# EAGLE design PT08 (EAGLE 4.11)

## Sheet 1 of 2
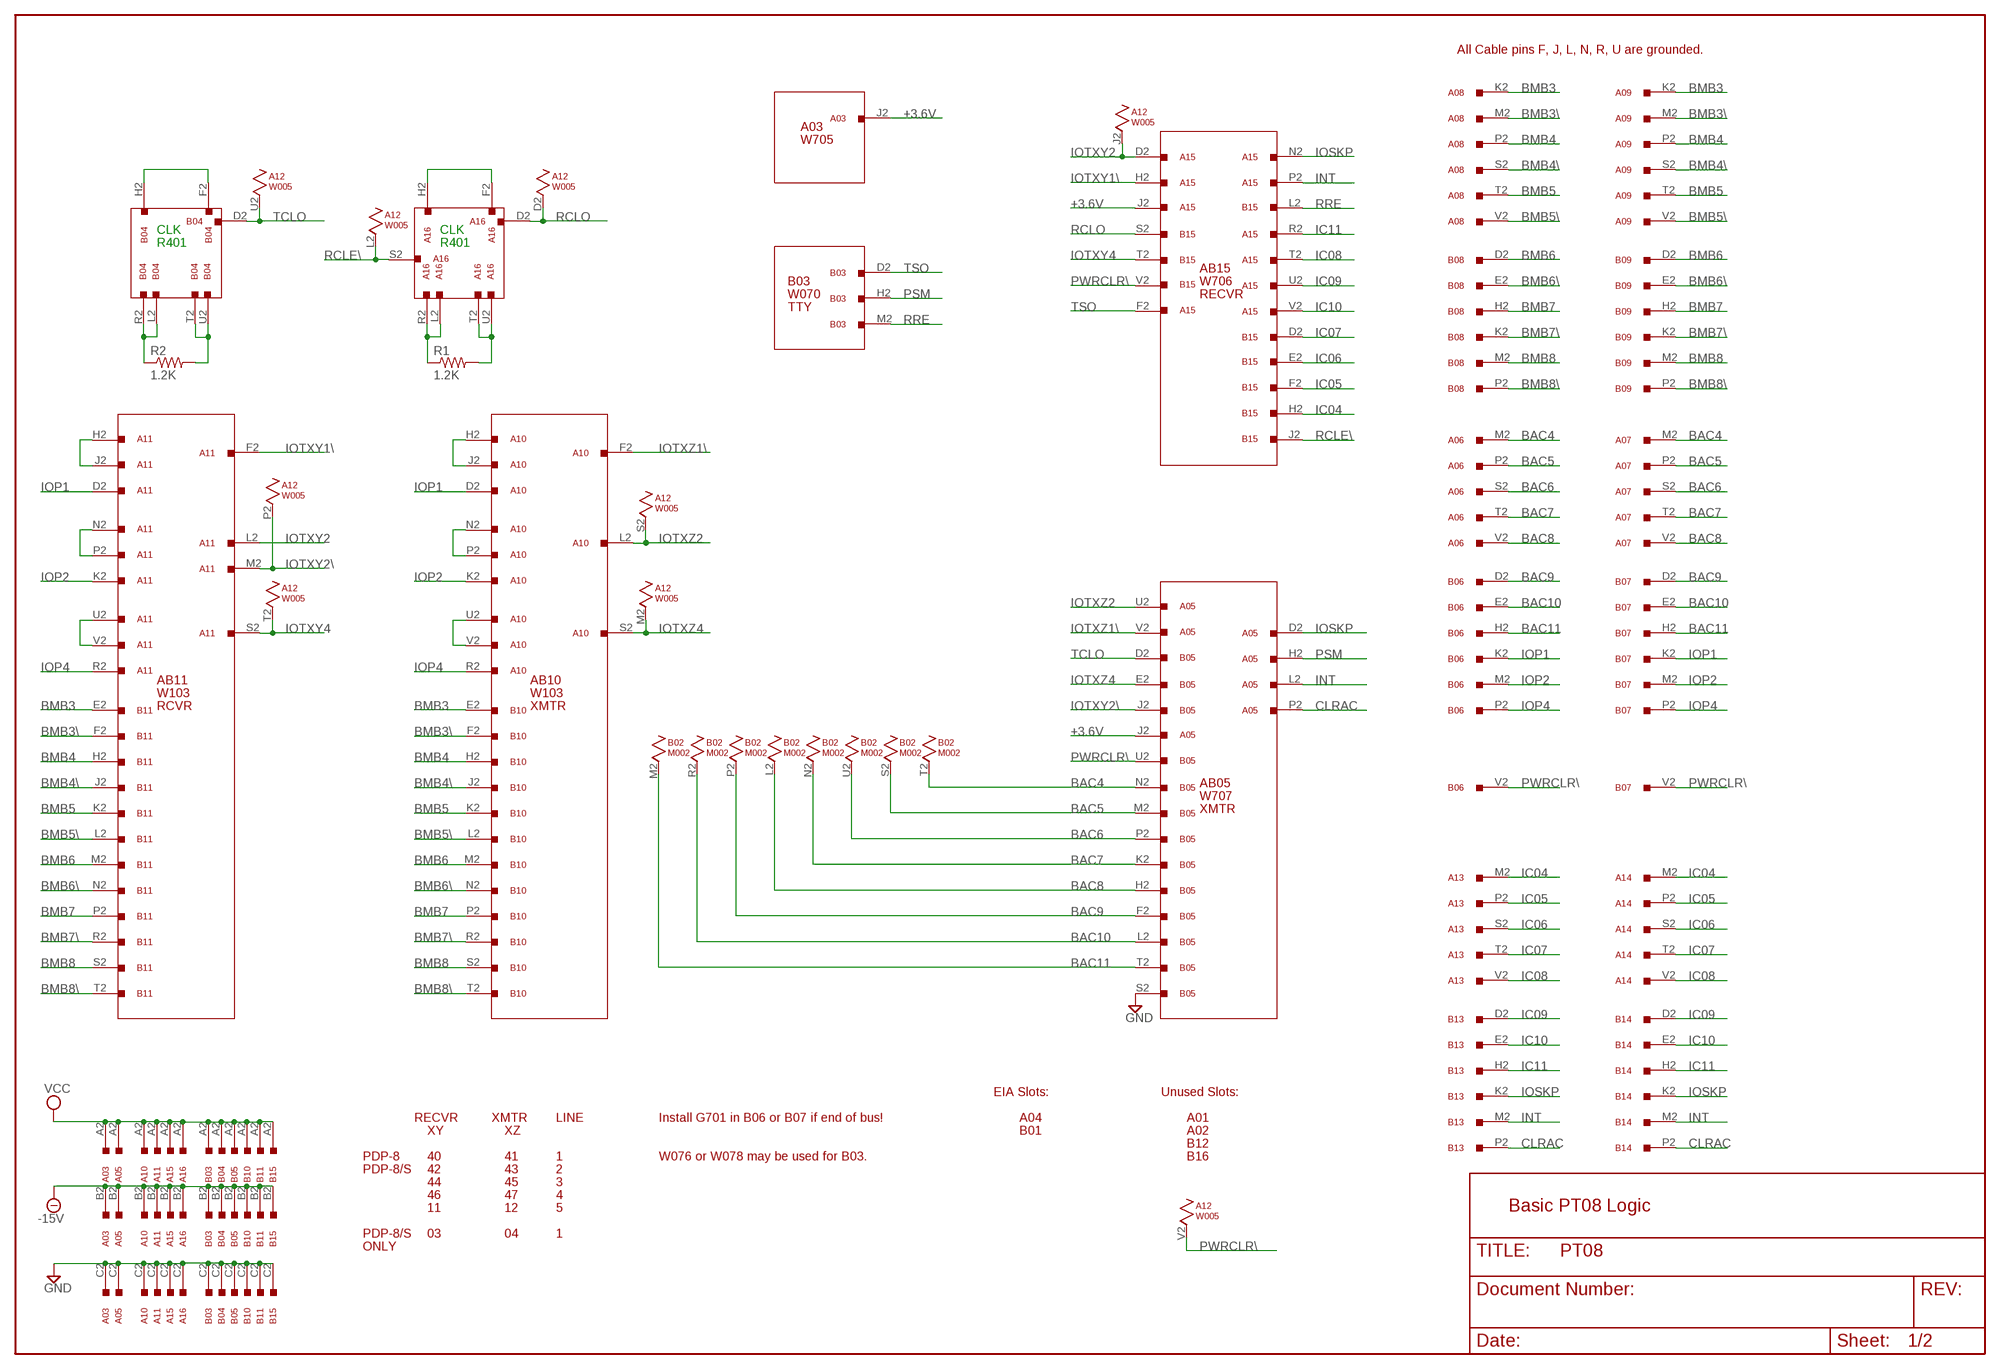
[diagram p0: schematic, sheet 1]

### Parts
A01  H807  [H807]
A02  H807  [H807]
A03  W705  W023  [H807]
A05  W707  W023  [H807]
A06  W011  [H807]
A07  W011  [H807]
A08  W011  [H807]
A09  W011  [H807]
A10  W103  W023  [H807]
A11  W103  W023  [H807]
A12  W005  [H807]
A13  W011  [H807]
A14  W011  [H807]
A15  W706  W023  [H807]
A16  R401  W023  [H807]
B02  M002  [H807]
B03  W076  W023  [H807]
B04  R401  W023  [H807]
B05  W707  W023  [H807]
B06  W011  [H807]
B07  W011  [H807]
B08  W011  [H807]
B09  W011  [H807]
B10  W103  W023  [H807]
B11  W103  W023  [H807]
B12  H807  [H807]
B13  W011  [H807]
B14  W011  [H807]
B15  W706  W023  [H807]
B16  H807  [H807]
R1  1.2K  R-US_0207/10  [0207/10]
R2  1.2K  R-US_0207/10  [0207/10]

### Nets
+3.6V: A03.J2 A05.J2 A15.J2
-15V [Power]: A03.B2 A05.B2 A10.B2 A11.B2 A15.B2 A16.B2 B03.B2 B04.B2 B05.B2 B10.B2 B11.B2 B15.B2 ; also sheet 2
BAC4: A06.M2 A07.M2 B02.T2 B05.N2
BAC5: A06.P2 A07.P2 B02.S2 B05.M2
BAC6: A06.S2 A07.S2 B02.U2 B05.P2
BAC7: A06.T2 A07.T2 B02.N2 B05.K2
BAC8: A06.V2 A07.V2 B02.L2 B05.H2
BAC9: B02.P2 B05.F2 B06.D2 B07.D2
BAC10: B02.R2 B05.L2 B06.E2 B07.E2
BAC11: B02.M2 B05.T2 B06.H2 B07.H2
BMB3: A08.K2 A09.K2 B10.E2 B11.E2
BMB3\: A08.M2 A09.M2 B10.F2 B11.F2
BMB4: A08.P2 A09.P2 B10.H2 B11.H2
BMB4\: A08.S2 A09.S2 B10.J2 B11.J2
BMB5: A08.T2 A09.T2 B10.K2 B11.K2
BMB5\: A08.V2 A09.V2 B10.L2 B11.L2
BMB6: B08.D2 B09.D2 B10.M2 B11.M2
BMB6\: B08.E2 B09.E2 B10.N2 B11.N2
BMB7: B08.H2 B09.H2 B10.P2 B11.P2
BMB7\: B08.K2 B09.K2 B10.R2 B11.R2
BMB8: B08.M2 B09.M2 B10.S2 B11.S2
BMB8\: B08.P2 B09.P2 B10.T2 B11.T2
CLRAC: A05.P2 B13.P2 B14.P2
GND [Power]: A03.C2 A05.C2 A10.C2 A11.C2 A15.C2 A16.C2 B03.C2 B04.C2 B05.C2 B05.S2 B10.C2 B11.C2 B15.C2 ; also sheet 2
IC04: A13.M2 A14.M2 B15.H2
IC05: A13.P2 A14.P2 B15.F2
IC06: A13.S2 A14.S2 B15.E2
IC07: A13.T2 A14.T2 B15.D2
IC08: A13.V2 A14.V2 A15.T2
IC09: A15.U2 B13.D2 B14.D2
IC10: A15.V2 B13.E2 B14.E2
IC11: A15.R2 B13.H2 B14.H2
INT: A05.L2 A15.P2 B13.M2 B14.M2
IOP1: A10.D2 A11.D2 B06.K2 B07.K2
IOP2: A10.K2 A11.K2 B06.M2 B07.M2
IOP4: A10.R2 A11.R2 B06.P2 B07.P2
IOSKP: A05.D2 A15.N2 B13.K2 B14.K2
IOTXY1\: A11.F2 A15.H2
IOTXY2: A11.L2 A12.J2 A15.D2
IOTXY2\: A11.M2 A12.P2 B05.J2
IOTXY4: A11.S2 A12.T2 B15.T2
IOTXZ1\: A05.V2 A10.F2
IOTXZ2: A05.U2 A10.L2 A12.S2
IOTXZ4: A10.S2 A12.M2 B05.E2
N$1: A10.U2 A10.V2
N$2: A16.F2 A16.H2
N$3: A16.L2 A16.R2 R1.1
N$4: A16.T2 A16.U2 R1.2
N$5: A10.H2 A10.J2
N$6: B04.F2 B04.H2
N$7: B04.L2 B04.R2 R2.1
N$8: B04.T2 B04.U2 R2.2
N$9: A11.U2 A11.V2
N$10: A11.H2 A11.J2
N$11: A10.N2 A10.P2
N$12: A11.N2 A11.P2
PSM: A05.H2 B03.H2 ; also sheet 2
PWRCLR\: A12.V2 B05.U2 B06.V2 B07.V2 B15.V2
RCLE\: A12.L2 A16.S2 B15.J2
RCLO: A12.D2 A16.D2 B15.S2
RRE: B03.M2 B15.L2
TCLO: A12.U2 B04.D2 B05.D2
TSO: A15.F2 B03.D2 ; also sheet 2
VCC [Power]: A03.A2 A05.A2 A10.A2 A11.A2 A15.A2 A16.A2 B03.A2 B04.A2 B05.A2 B10.A2 B11.A2 B15.A2 ; also sheet 2
Unconnected: A03.D2 A03.E2 A03.F2 A03.H2 A03.K2 A03.L2 A03.M2 A03.N2 A03.P2 A03.R2 A03.S2 A03.T2 A03.U2 A03.V2 A05.E2 A05.F2 A05.K2 A05.M2 A05.N2 A05.R2 A05.S2 A05.T2 A06.D2 A06.E2 A06.H2 A06.K2 A07.D2 A07.E2 A07.H2 A07.K2 A08.D2 A08.E2 A08.H2 A09.D2 A09.E2 A09.H2 A10.E2 A10.M2 A10.T2 A11.E2 A11.T2 A12.E2 A12.F2 A12.H2 A12.K2 A12.N2 A12.R2 A13.D2 A13.E2 A13.H2 A13.K2 A14.D2 A14.E2 A14.H2 A14.K2 A15.E2 A15.K2 A15.L2 A15.M2 A15.S2 A16.E2 A16.J2 A16.K2 A16.M2 A16.N2 A16.P2 A16.V2 B02.F2 B02.H2 B02.J2 B02.K2 B02.V2 B03.F2 B03.J2 B03.L2 B03.N2 B03.R2 B03.S2 B03.T2 B03.U2 B03.V2 B04.E2 B04.J2 B04.K2 B04.M2 B04.N2 B04.P2 B04.S2 B04.V2 B05.R2 B05.V2 B06.S2 B06.T2 B07.S2 B07.T2 B08.S2 B08.T2 B08.V2 B09.S2 B09.T2 B09.V2 B10.D2 B10.U2 B10.V2 B11.D2 B11.U2 B11.V2 B13.S2 B13.T2 B13.V2 B14.S2 B14.T2 B14.V2 B15.K2 B15.M2 B15.N2 B15.P2 B15.R2 B15.U2

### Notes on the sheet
- All Cable pins F, J, L, N, R, U are grounded.
- A03
- W705
- CLK | CLK
- R401 | R401
- AB15
- B03 | W706
- W070 | RECVR
- TTY
- AB11 | AB10
- W103 | W103
- RCVR | XMTR
- AB05
- W707
- XMTR
- EIA Slots: | Unused Slots:
- RECVR | XMTR | LINE | Install G701 in B06 or B07 if end of bus! | A04
- XY | XZ | B01
- PDP-8 | 40 | 41 | 1 | W076 or W078 may be used for B03.
- PDP-8/S | 42 | 43 | 2
- 44 | 45 | 3
- 46 | 47 | 4
- 11 | 12 | 5 | Basic PT08 Logic
- PDP-8/S | 03 | 04 | 1
- ONLY

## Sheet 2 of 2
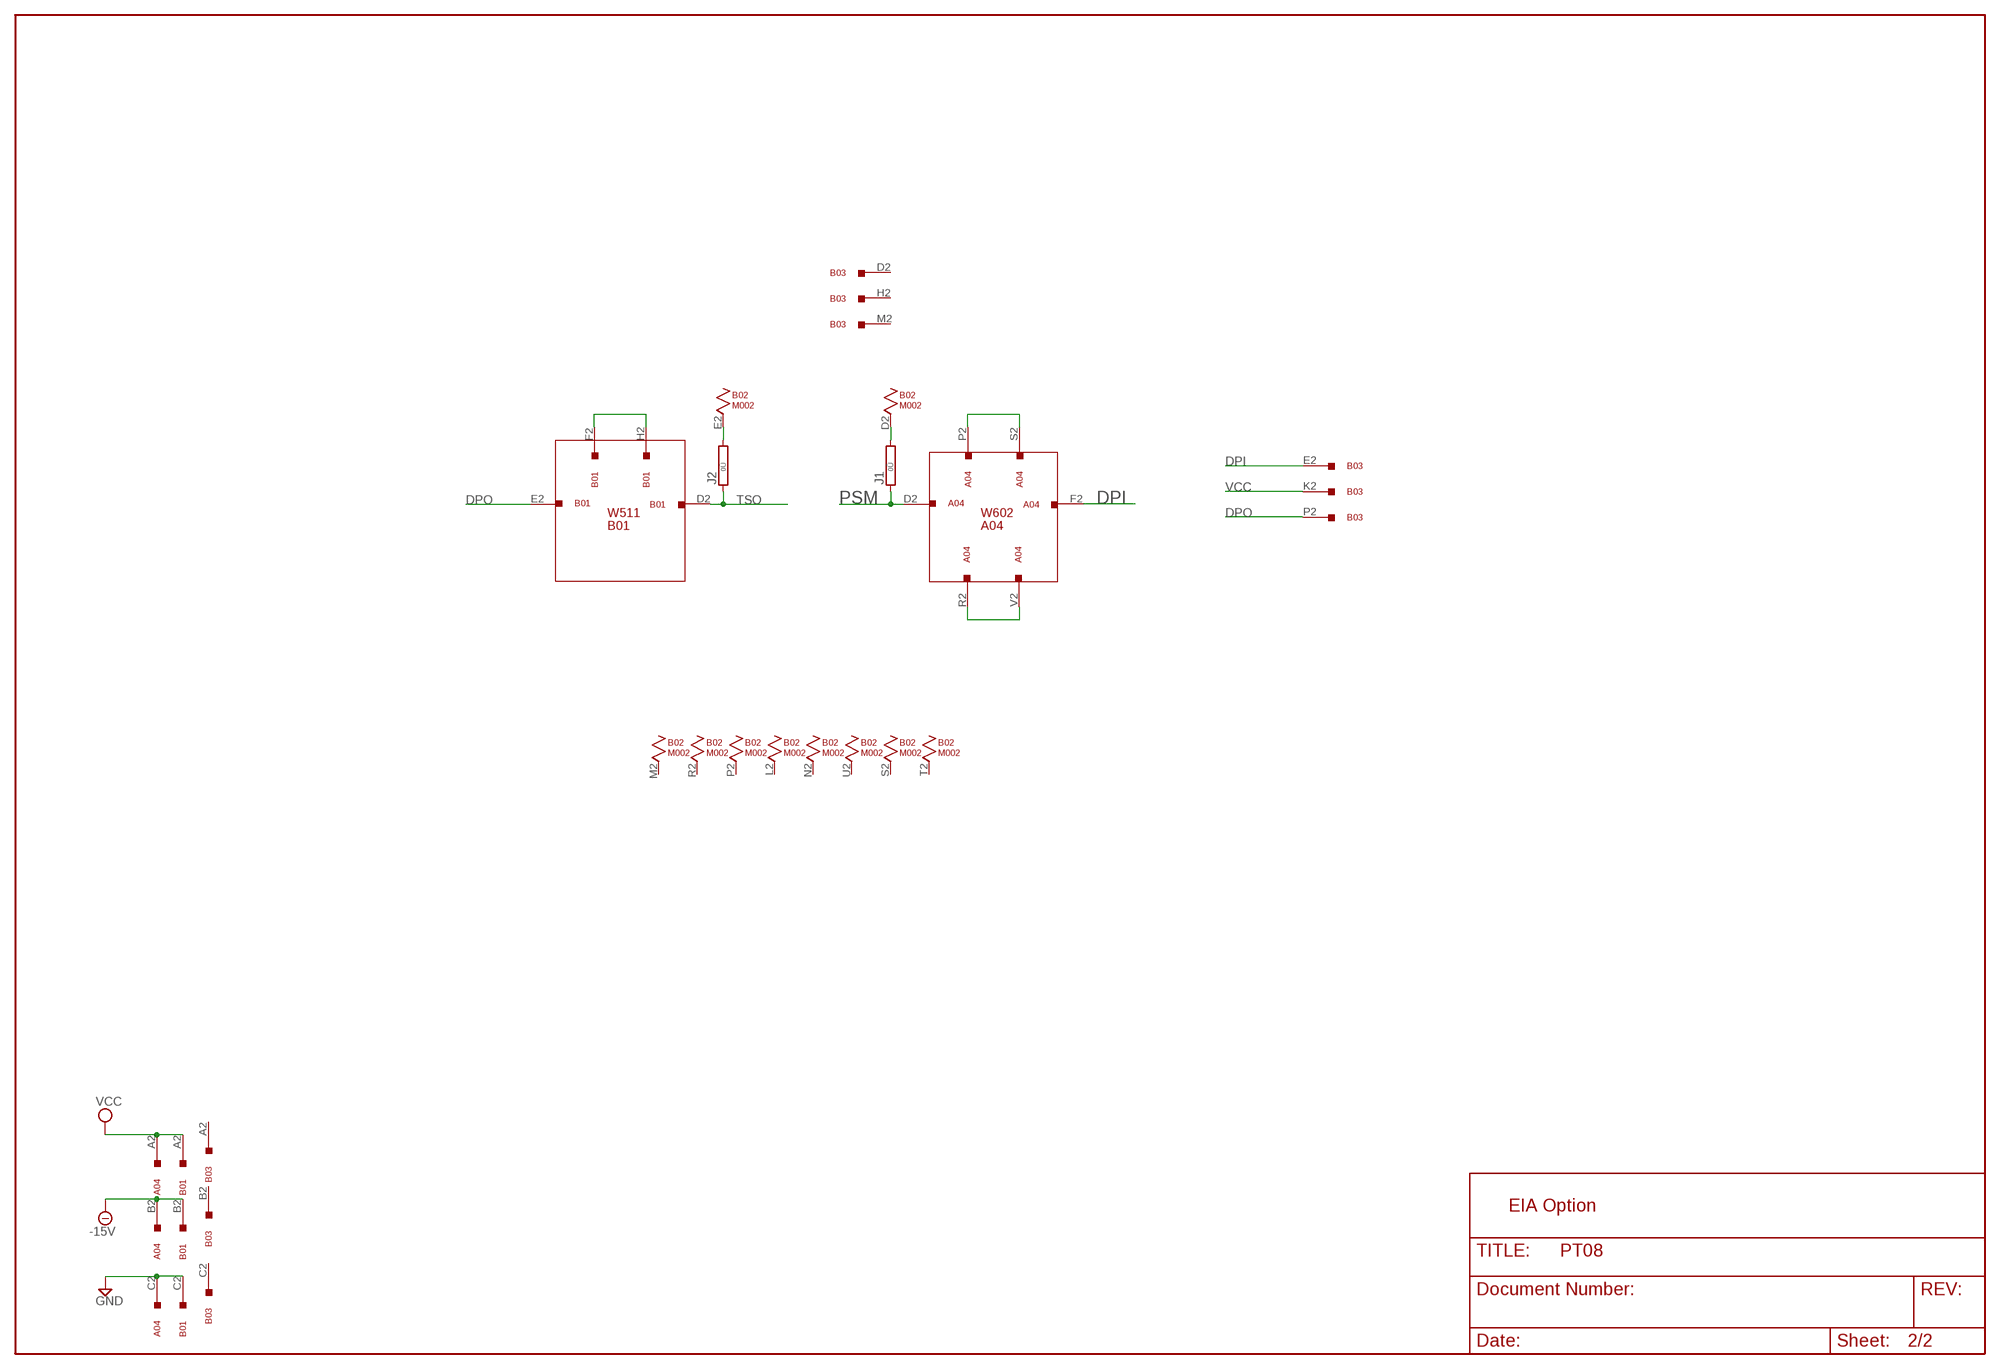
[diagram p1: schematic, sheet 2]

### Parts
A04  W602  W023  [H807]
B01  W511  W023  [H807]
J1  0R  [0R/10]
J2  0R  [0R/10]

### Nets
-15V [Power]: A04.B2 B01.B2 ; also sheet 1
DPI: A04.F2 B03.E2
DPO: B01.E2 B03.P2
GND [Power]: A04.C2 B01.C2 ; also sheet 1
N$13: A04.P2 A04.S2
N$14: A04.R2 A04.V2
N$15: B02.D2 J1.2
N$16: B01.F2 B01.H2
N$17: B02.E2 J2.2
PSM: A04.D2 J1.1 ; also sheet 1
TSO: B01.D2 J2.1 ; also sheet 1
VCC [Power]: A04.A2 B01.A2 B03.K2 ; also sheet 1
Unconnected: A04.E2 A04.H2 A04.J2 A04.K2 A04.L2 A04.M2 A04.N2 A04.T2 A04.U2 B01.J2 B01.K2 B01.L2 B01.M2 B01.N2 B01.P2 B01.R2 B01.S2 B01.T2 B01.U2 B01.V2

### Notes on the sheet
- W511 | W602
- B01 | A04
- EIA Option

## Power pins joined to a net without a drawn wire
-15V: A12.B2
GND: A06.C2 A06.F2 A06.J2 A06.L2 A06.N2 A06.R2 A06.U2 A07.C2 A07.F2 A07.J2 A07.L2 A07.N2 A07.R2 A07.U2 A08.C2 A08.F2 A08.J2 A08.L2 A08.N2 A08.R2 A08.U2 A09.C2 A09.F2 A09.J2 A09.L2 A09.N2 A09.R2 A09.U2 A12.C2 A13.C2 A13.F2 A13.J2 A13.L2 A13.N2 A13.R2 A13.U2 A14.C2 A14.F2 A14.J2 A14.L2 A14.N2 A14.R2 A14.U2 B02.C2(GND) B06.C2 B06.F2 B06.J2 B06.L2 B06.N2 B06.R2 B06.U2 B07.C2 B07.F2 B07.J2 B07.L2 B07.N2 B07.R2 B07.U2 B08.C2 B08.F2 B08.J2 B08.L2 B08.N2 B08.R2 B08.U2 B09.C2 B09.F2 B09.J2 B09.L2 B09.N2 B09.R2 B09.U2 B13.C2 B13.F2 B13.J2 B13.L2 B13.N2 B13.R2 B13.U2 B14.C2 B14.F2 B14.J2 B14.L2 B14.N2 B14.R2 B14.U2
VCC: B02.A2(VCC)

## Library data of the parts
A01 A02 B12 B16 = dec-m:H807: Empty card slot
A03-A05 A10 A11 A15 A16 B01 B03-B05 B10 B11 B15 = dec-m:W023: One-sided 18 pin connector/cable.
A06-A09 A13 A14 B06-B09 B13 B14 = dec-m:W011: One-sided 9 pin connector/cable with grounds (Negibus).
A12 = dec-m:W005: 15 Clamped Loads
B02 = dec-m:M002: 15 Clamped Loads
J1 J2 = jumper:0R: Bridge 0R 10mm
R1 R2 = rcl:R-US_: RESISTOR, American symbol

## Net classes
1 Power: width 0.508 mm

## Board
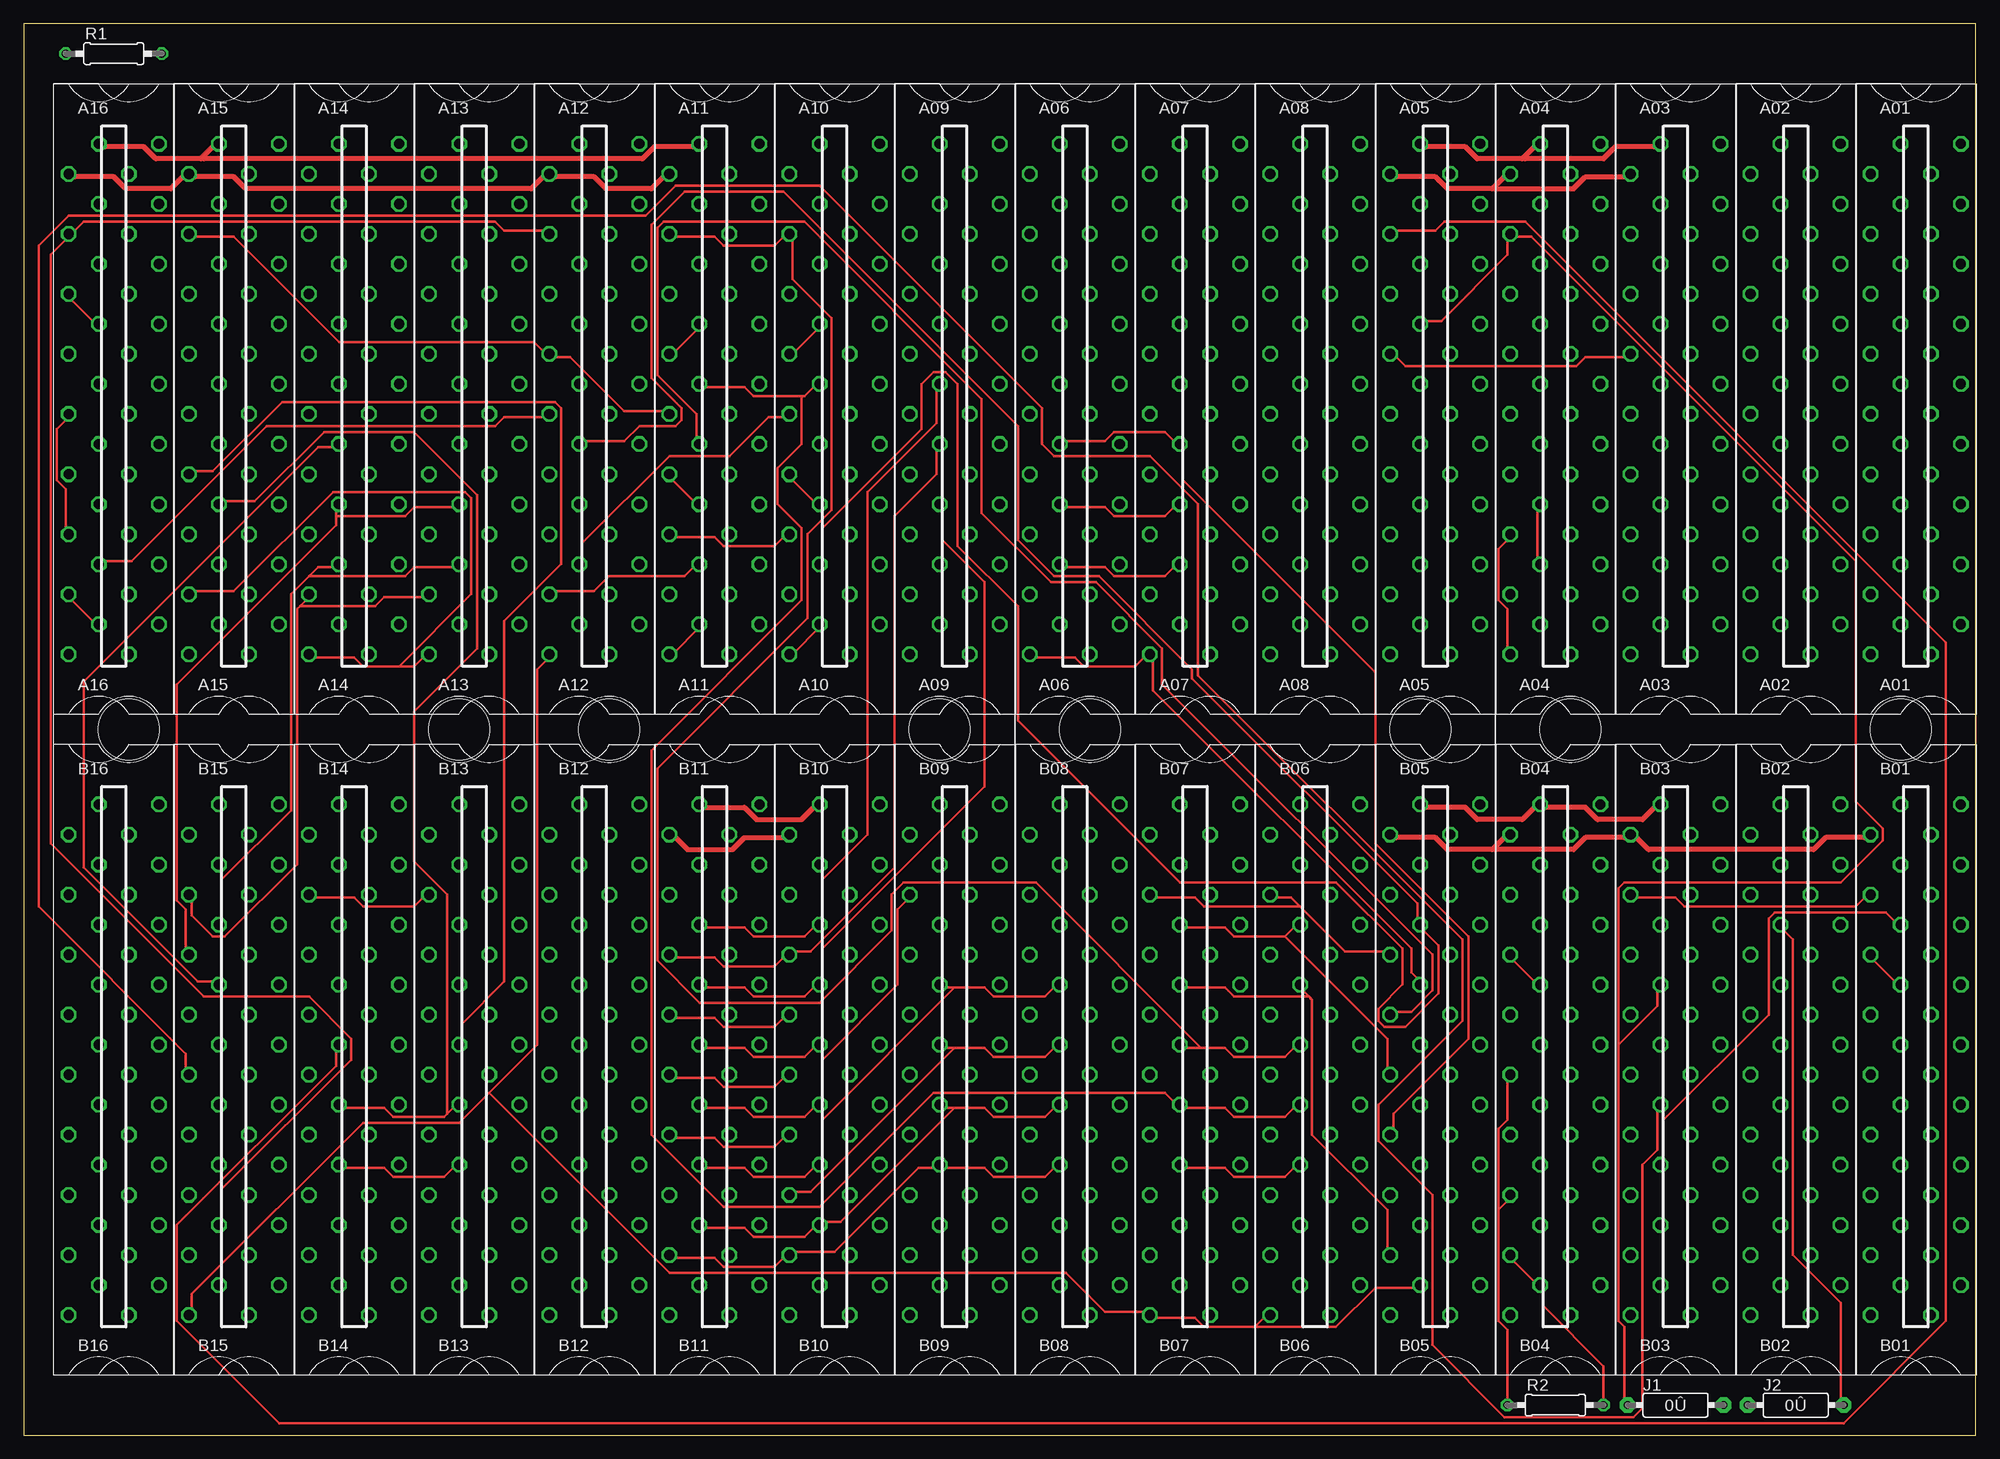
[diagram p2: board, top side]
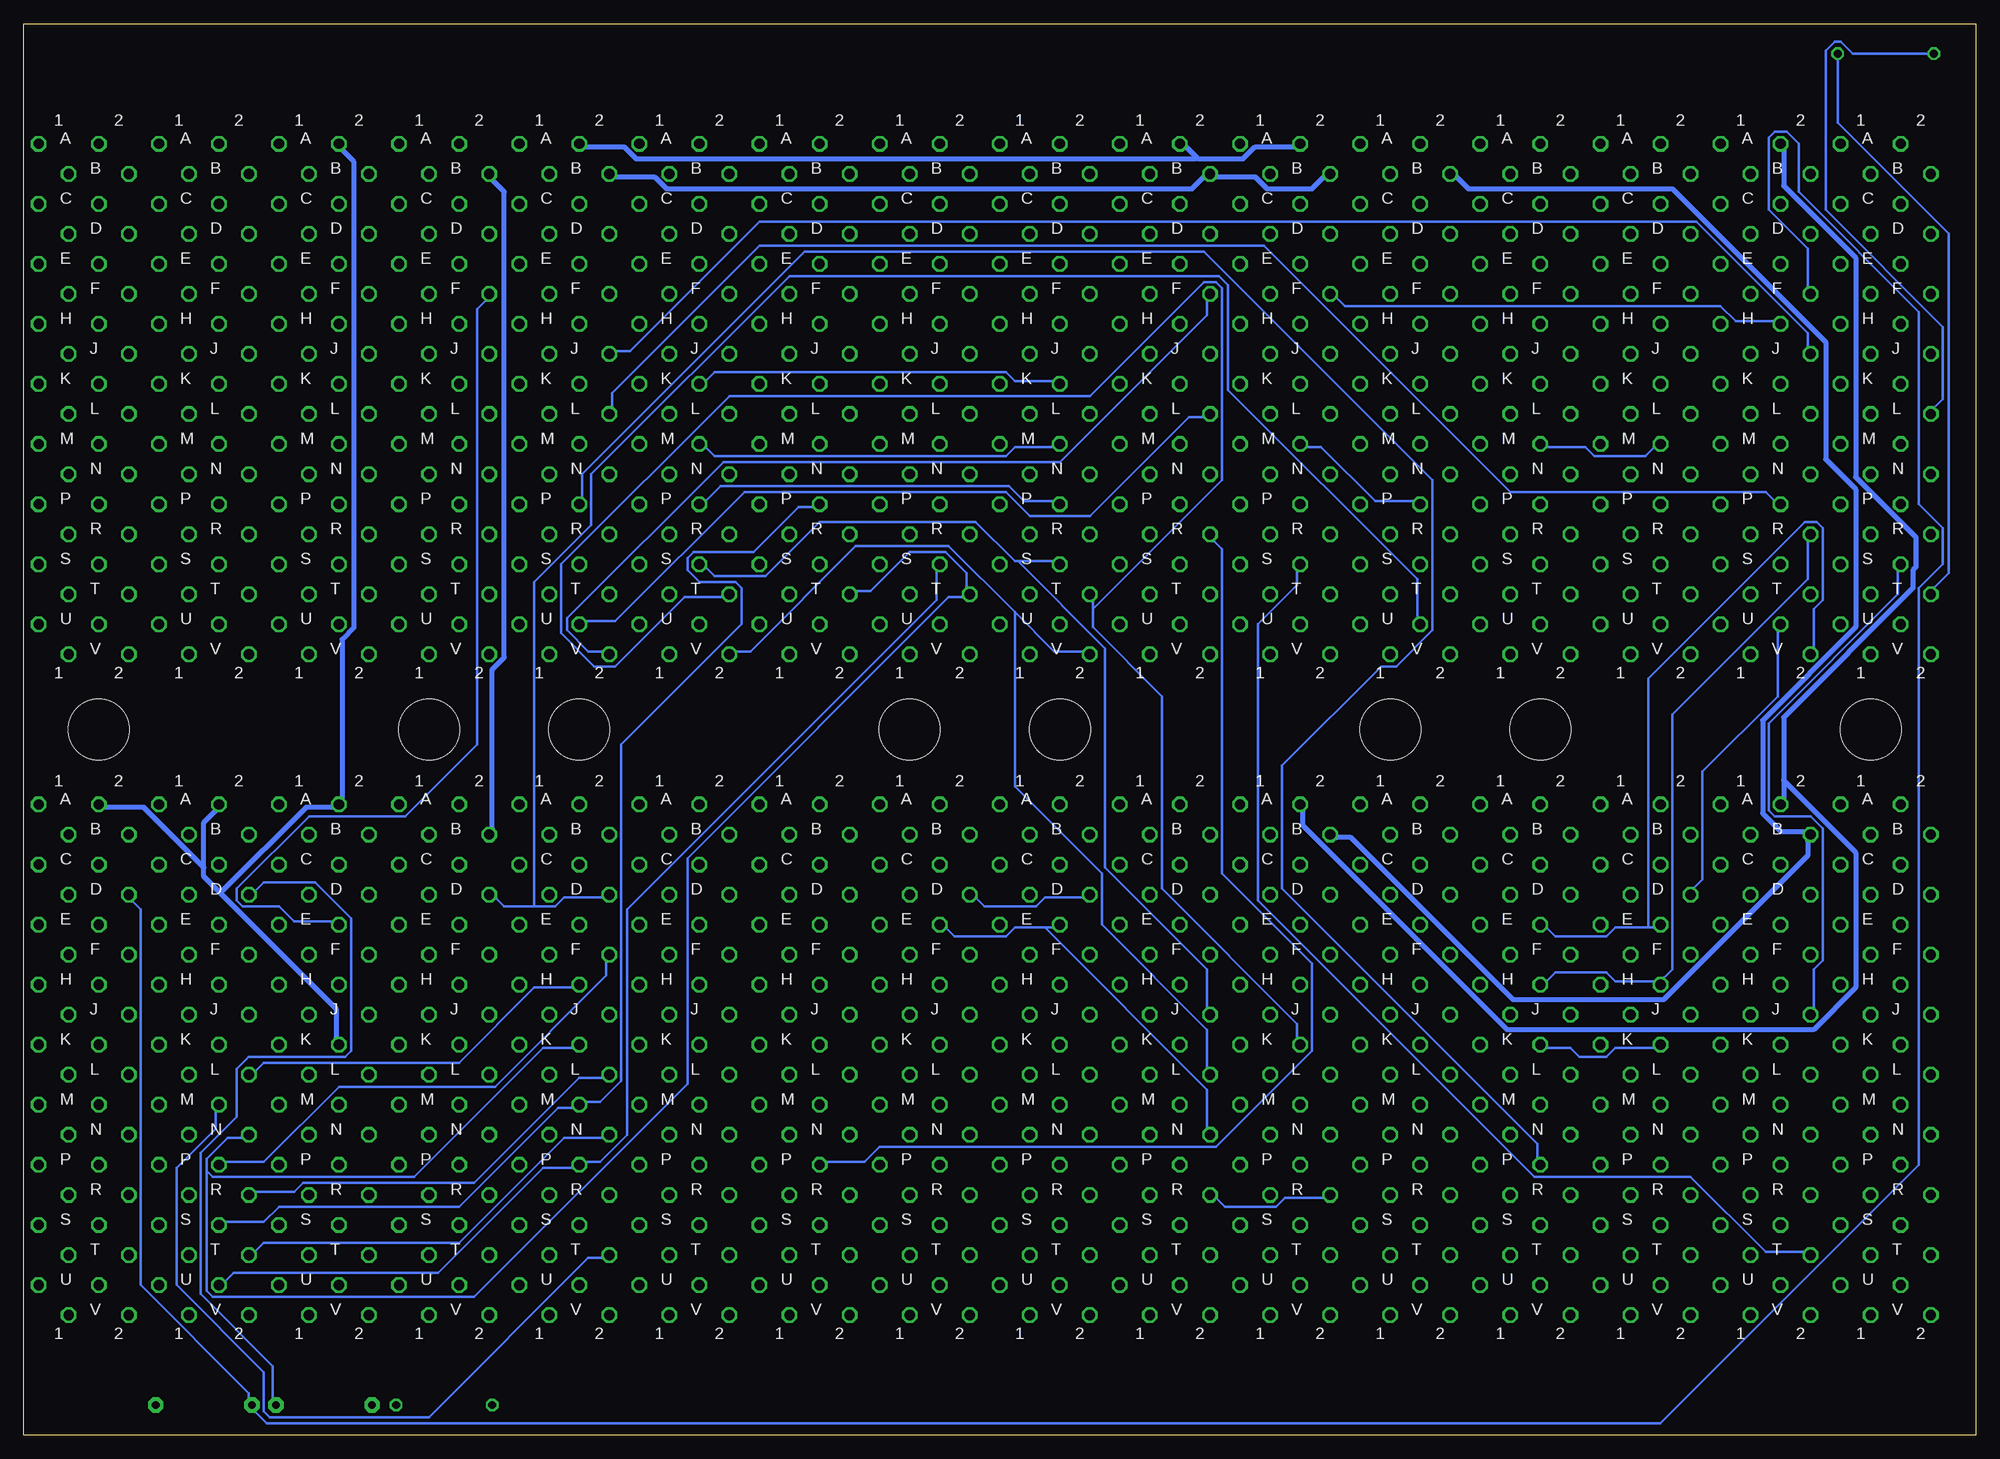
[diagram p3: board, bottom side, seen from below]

Size 206.38 x 149.22 mm. Coordinates in mm from the lower left corner, seen from the top.
Outline: 0,0 206.38,0 206.38,149.22 0,149.22 0,0
Copper layers (1*16): Top 0.035mm / dielectric 1.5mm / Bottom 0.035mm
Design rules "10mils": minimum track width 10mil, minimum drill 24mil, track to track 10mil, track to pad 10mil, pad to pad 10mil, via to via 10mil, smd to smd 10mil, copper to edge 25mil, drill to drill 10mil, minimum pad ring 10mil, minimum via ring 8mil, stop-mask expansion 0mil, vias tented up to drill 0mil, thermal gap 10mil

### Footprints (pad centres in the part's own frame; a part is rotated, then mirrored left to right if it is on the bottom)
H807 = drill 1.092 octagon: A1 4.763,28.575; A2 -1.587,28.575; B1 1.587,25.4; B2 -4.763,25.4; C1 4.763,22.225; C2 -1.587,22.225; D1 1.587,19.05; D2 -4.763,19.05; E1 4.763,15.875; E2 -1.587,15.875; F1 1.587,12.7; F2 -4.763,12.7; H1 4.763,9.525; H2 -1.587,9.525; J1 1.587,6.35; J2 -4.763,6.35; K1 4.763,3.175; K2 -1.587,3.175; L1 1.587,0; L2 -4.763,0; M1 4.763,-3.175; M2 -1.587,-3.175; N1 1.587,-6.35; N2 -4.763,-6.35; P1 4.763,-9.525; P2 -1.587,-9.525; R1 1.587,-12.7; R2 -4.763,-12.7; S1 4.763,-15.875; S2 -1.587,-15.875; T1 1.587,-19.05; T2 -4.763,-19.05; U1 4.763,-22.225; U2 -1.587,-22.225; V1 1.587,-25.4; V2 -4.763,-25.4
0R/10 = drill 0.813 pad 1.6 octagon: 1 -5.08,0; 2 5.08,0
0207/10 = drill 0.813 octagon: 1 -5.08,0; 2 5.08,0
CBLOCK = hole 6.452: 7.938,68.263; 42.862,68.263

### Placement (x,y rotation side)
A01  200.03,107.95 0 top
A02  187.32,107.95 0 top
A03  174.62,107.95 0 top
A04  161.93,107.95 0 top
A05  149.22,107.95 0 top
A06  111.12,107.95 0 top
A07  123.83,107.95 0 top
A08  136.53,107.95 0 top
A09  98.42,107.95 0 top
A10  85.72,107.95 0 top
A11  73.03,107.95 0 top
A12  60.33,107.95 0 top
A13  47.62,107.95 0 top
A14  34.92,107.95 0 top
A15  22.23,107.95 0 top
A16  9.53,107.95 0 top
B01  200.03,38.1 0 top
B02  187.32,38.1 0 top
B03  174.62,38.1 0 top
B04  161.93,38.1 0 top
B05  149.22,38.1 0 top
B06  136.53,38.1 0 top
B07  123.83,38.1 0 top
B08  111.12,38.1 0 top
B09  98.42,38.1 0 top
B10  85.72,38.1 0 top
B11  73.03,38.1 0 top
B12  60.33,38.1 0 top
B13  47.62,38.1 0 top
B14  34.92,38.1 0 top
B15  22.23,38.1 0 top
B16  9.53,38.1 0 top
J1  174.62,3.17 0 top
J2  187.32,3.17 0 top
R1  9.53,146.05 0 top
R2  161.93,3.17 0 top
U$1  [CBLOCK]  3.17,6.35 0 top
U$2  [CBLOCK]  53.98,6.35 0 top
U$3  [CBLOCK]  104.78,6.35 0 top
U$4  [CBLOCK]  155.57,6.35 0 top

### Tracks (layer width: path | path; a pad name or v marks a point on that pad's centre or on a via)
+3.6V
  Top 0.254: A03.J2 169.23,113.98 165.1,113.98 164.15,113.03 146.05,113.03 145.1,113.98 A05.J2
  Bottom 0.254: A15.J2 17.78,114.94 17.78,116.52 29.53,128.27 128.59,128.27 142.24,114.62 143.83,114.62 A05.J2
-15V
  Top 0.508: B10.B2 80.33,63.18 76.2,63.18 74.93,61.91 70.17,61.91 68.9,63.18 B11.B2 | 155.42,62.07 156.53,63.18 B04.B2 | 155.42,62.07 155.26,61.91 150.5,61.91 149.22,63.18 145.1,63.18 B05.B2 | 155.42,62.07 155.57,61.91 163.83,61.91 165.1,63.18 169.23,63.18 B03.B2 170.5,63.18 171.77,61.91 189.23,61.91 190.5,63.18 194.63,63.18 B01.B2 | 155.42,131.92 156.53,133.03 A04.B2 | 155.42,131.92 155.26,131.76 150.5,131.76 149.22,133.03 145.1,133.03 A05.B2 | A03.B2 169.23,133.03 165.1,133.03 163.83,131.76 155.57,131.76 155.42,131.92 | A16.B2 5.4,133.03 9.53,133.03 10.79,131.76 15.56,131.76 16.83,133.03 A15.B2 18.1,133.03 22.23,133.03 23.5,131.76 53.66,131.76 54.93,133.03 A12.B2 56.2,133.03 60.33,133.03 61.59,131.76 66.36,131.76 67.63,133.03 A11.B2
  Bottom 0.508: B11.B2 67.63,63.18 66.04,63.18 48.9,46.04 33.02,46.04 17.78,61.28 17.78,62.87 B15.B2 18.1,63.82 20.64,63.82 22.54,65.72 22.54,75.56 12.7,85.41 12.7,100.01 15.88,103.19 15.88,115.57 32.07,131.76 53.66,131.76 54.93,133.03 A12.B2 | A11.B2 68.9,133.03 70.17,131.76 74.93,131.76 76.2,133.03 80.33,133.03 A10.B2 81.6,133.03 82.87,131.76 138.43,131.76 139.7,133.03 143.83,133.03 A05.B2 | B04.B2 156.84,64.14 156.84,80.96 155.57,82.23 155.57,131.44 156.84,132.72 A04.B2
BAC4
  Top 0.254: A06.M2 110.17,105.09 114.3,105.09 115.25,106.05 120.65,106.05 121.6,105.09 A07.M2 122.56,104.14 122.56,100.97 142.88,80.64 142.88,62.55 152.72,52.7 152.72,41.91 144.78,33.97 144.78,32.38 B05.N2
  Bottom 0.254: B05.N2 145.1,31.43 149.22,31.43 160.34,20.32 180.97,20.32 181.93,19.37 B02.T2
BAC5
  Top 0.254: A06.P2 110.17,98.11 114.3,98.11 115.25,97.16 120.65,97.16 121.6,98.11 A07.P2
  Bottom 0.254: B02.S2 185.1,22.54 180.97,22.54 179.39,24.13 160.34,24.13 149.86,34.61 148.27,34.61 B05.M2 147,35.24 145.41,35.24 143.19,37.47 143.19,73.03 130.49,85.72 130.49,89.53 131.13,90.17 134.94,90.17 136.21,91.44 136.21,92.71 135.57,93.34 129.22,93.34 124.46,98.11 122.87,98.11 A07.P2
BAC6
  Top 0.254: A06.S2 110.17,91.76 114.3,91.76 115.25,90.81 120.65,90.81 121.6,91.76 A07.S2
  Bottom 0.254: B02.U2 185.1,16.19 184.15,17.14 162.56,17.14 151.45,28.26 148.27,28.26 B05.P2 147,28.89 145.41,28.89 142.56,31.75 142.56,55.56 109.86,88.27 109.86,91.44 A06.S2
BAC7
  Bottom 0.254: A07.T2 118.43,89.22 116.84,89.22 112.71,93.34 108.9,93.34 106.68,91.12 106.68,89.53 A06.T2 107,88.58 108.58,88.58 136.21,60.96 136.21,37.15 158.75,14.61 186.37,14.61 187.01,15.24 187.01,27.94 | 187.01,27.94 186.37,27.3 165.1,27.3 151.45,40.96 148.27,40.96 B05.K2 | 187.01,27.94 187.01,29.21 184.78,31.43 183.2,31.43 B02.N2
BAC8
  Top 0.254: A06.V2 107,82.23 111.12,82.23 112.08,81.28 117.47,81.28 118.43,82.23 A07.V2 119.38,81.92 119.38,78.74 146.69,51.44 146.69,48.9 147.32,48.26 B05.H2
  Bottom 0.254: B05.H2 148.27,47.31 152.4,47.31 160.34,39.37 180.97,39.37 181.93,38.42 B02.L2
BAC9
  Top 0.254: 134.94,55.88 133.99,56.83 132.4,56.83 B06.D2 | 134.94,55.88 139.7,51.12 143.83,51.12 B05.F2 | 134.94,55.88 124.78,55.88 123.83,56.83 119.7,56.83 B07.D2
  Bottom 0.254: B02.P2 185.1,28.89 180.97,28.89 173.04,36.83 156.53,36.83 144.78,48.58 144.78,50.16 B05.F2
BAC10
  Top 0.254: 133.35,52.7 127.95,52.7 127,53.66 122.87,53.66 B07.E2 | 133.35,52.7 134.3,53.66 B06.E2 | 133.35,52.7 144.15,41.91 144.15,38.73 B05.L2
  Bottom 0.254: B02.R2 181.93,25.72 177.8,25.72 176.85,26.67 158.75,26.67 147.64,37.78 145.1,37.78 B05.L2
BAC11
  Top 0.254: 135.89,46.35 135.25,46.99 B06.H2 | 135.89,46.35 136.21,46.04 136.21,31.75 144.15,23.81 144.15,19.68 B05.T2 | 135.89,46.35 127.95,46.35 127,47.31 122.87,47.31 B07.H2
  Bottom 0.254: B02.M2 186.06,34.29 186.06,32.38 190.18,28.26 190.18,15.88 180.97,6.67 180.97,2.54 180.34,1.91 163.51,1.91 146.69,18.73 145.1,18.73 B05.T2
BMB3
  Top 0.254: B11.E2 72.07,53.66 76.2,53.66 77.15,52.7 82.55,52.7 83.5,53.66 B10.E2 84.45,54.61 84.45,58.74 89.22,63.5 89.22,99.69 96.52,107 96.52,110.49 A09.K2
  Bottom 0.254: A09.K2 97.47,111.44 101.6,111.44 102.55,112.39 133.35,112.39 134.3,111.44 A08.K2
BMB3\
  Top 0.254: B11.F2 68.9,50.48 73.03,50.48 73.98,49.53 79.38,49.53 80.33,50.48 B10.F2 81.6,51.12 83.19,51.12 92.08,60.01 92.08,97.16 96.52,101.6 96.52,104.14 A09.M2
  Bottom 0.254: A09.M2 97.47,104.46 101.6,104.46 102.55,103.5 133.35,103.5 134.3,104.46 A08.M2
BMB4
  Top 0.254: B11.H2 72.07,47.31 76.2,47.31 77.15,46.35 82.55,46.35 83.5,47.31 B10.H2 84.45,48.26 84.45,51.44 101.6,68.58 101.6,90.17 97.16,94.61 97.16,97.79 A09.P2
  Bottom 0.254: A09.P2 97.47,98.74 100.65,98.74 102.23,100.33 132.72,100.33 134.3,98.74 A08.P2
BMB4\
  Top 0.254: B11.J2 68.9,44.13 73.03,44.13 73.98,43.18 79.38,43.18 80.33,44.13 B10.J2
  Bottom 0.254: 101.28,92.39 101.6,92.39 105.73,96.52 122.24,96.52 127.95,90.81 133.35,90.81 134.3,91.76 A08.S2 | 101.28,92.39 97.47,92.39 A09.S2 | 101.28,92.39 92.08,83.19 92.08,60.01 81.28,49.21 81.28,45.09 B10.J2
BMB5
  Top 0.254: B11.K2 72.07,40.96 76.2,40.96 77.15,40.01 82.55,40.01 83.5,40.96 B10.K2
  Bottom 0.254: 93.34,87.31 93.34,85.41 86.04,78.11 86.04,57.78 71.75,43.5 71.75,41.91 B11.K2 | 93.34,87.31 93.34,88.27 A09.T2 | 93.34,87.31 79.69,100.97 79.69,121.28 80.33,121.92 81.6,121.92 93.66,109.86 131.76,109.86 149.54,92.08 149.54,84.77 146.05,81.28 143.83,81.28 136.53,88.58 132.4,88.58 A08.T2
BMB5\
  Top 0.254: B11.L2 68.9,37.78 73.03,37.78 73.98,36.83 79.38,36.83 80.33,37.78 B10.L2
  Bottom 0.254: 101.6,87 108.58,93.98 118.43,93.98 129.54,82.87 131.13,82.87 A08.V2 | 101.6,87 97.47,82.87 94.3,82.87 A09.V2 | 101.6,87 101.6,68.58 92.39,59.37 92.39,53.98 81.28,42.86 81.28,38.73 B10.L2
BMB6
  Top 0.254: B11.M2 72.07,34.61 76.2,34.61 77.15,33.66 82.55,33.66 83.5,34.61 B10.M2 84.45,35.56 84.45,39.69 92.39,47.62 92.39,55.56 93.34,56.52 B09.D2
  Bottom 0.254: B09.D2 94.3,56.83 98.42,56.83 99.38,55.88 104.78,55.88 105.73,56.83 B08.D2
BMB6\
  Top 0.254: B11.N2 68.9,31.43 73.03,31.43 73.98,30.48 79.38,30.48 80.33,31.43 B10.N2
  Bottom 0.254: 98.42,53.66 101.6,53.66 102.55,52.7 107.95,52.7 108.9,53.66 B08.E2 | 98.42,53.66 97.47,53.66 B09.E2 | 98.42,53.66 81.28,36.51 81.28,32.38 B10.N2
BMB7
  Top 0.254: B11.P2 72.07,28.26 76.2,28.26 77.15,27.3 82.55,27.3 83.5,28.26 B10.P2 84.45,29.21 84.45,33.34 98.42,47.31 | 98.42,47.31 101.6,47.31 102.55,46.35 107.95,46.35 108.9,47.31 B08.H2 | 98.42,47.31 97.47,47.31 B09.H2
BMB7\
  Top 0.254: 98.42,40.96 101.6,40.96 102.55,40.01 107.95,40.01 108.9,40.96 B08.K2 | 98.42,40.96 97.47,40.96 B09.K2 | 98.42,40.96 83.19,25.72 81.6,25.72 B10.R2
  Bottom 0.254: B11.R2 68.9,25.08 73.03,25.08 73.98,24.13 79.38,24.13 80.33,25.08 B10.R2
BMB8
  Top 0.254: B11.S2 72.07,21.91 76.2,21.91 77.15,20.95 82.55,20.95 83.5,21.91 B10.S2 84.77,22.54 86.36,22.54 98.42,34.61 | 98.42,34.61 101.6,34.61 102.55,33.66 107.95,33.66 108.9,34.61 B08.M2 | 98.42,34.61 97.47,34.61 B09.M2
BMB8\
  Top 0.254: B11.T2 68.9,18.73 73.03,18.73 73.98,17.78 79.38,17.78 80.33,18.73 B10.T2 81.6,19.37 85.72,19.37 94.61,28.26 96.2,28.26 B09.P2 97.47,28.26 101.6,28.26 102.55,27.3 107.95,27.3 108.9,28.26 B08.P2
CLRAC
  Top 0.254: B14.P2 33.97,28.26 38.1,28.26 39.05,27.3 44.45,27.3 45.4,28.26 B13.P2
  Bottom 0.254: A05.P2 147.32,99.06 147.32,101.6 123.83,125.09 81.6,125.09 57.47,100.97 57.47,85.09 61.28,81.28 62.87,81.28 73.34,70.8 73.34,57.78 46.35,30.8 46.35,29.21 B13.P2
DPI
  Bottom 0.254: B03.E2 173.67,54.29 177.8,54.29 179.39,55.88 183.2,55.88 183.83,56.52 183.83,57.78 176.21,65.41 166.05,65.41 158.43,73.03 158.43,119.06 157.48,120.02 A04.F2
DPO
  Top 0.254: B03.P2 173.35,29.21 173.35,33.34 184.47,44.45 184.47,54.61 185.1,55.24 196.85,55.24 197.8,54.29 B01.E2
IC04
  Top 0.254: B15.H2 20,47.94 18.41,47.94 6.35,60.01 6.35,79.69 31.11,104.46 32.7,104.46 A14.M2
  Bottom 0.254: A13.M2 45.4,104.46 41.27,104.46 40.32,103.5 34.92,103.5 33.97,104.46 A14.M2
IC05
  Top 0.254: 33.02,97.16 33.02,97.79 A14.P2 | 33.02,97.16 33.02,96.2 16.19,79.38 16.19,56.52 17.14,55.56 17.14,51.44 B15.F2 | 33.02,97.16 40.32,97.16 41.27,98.11 45.4,98.11 A13.P2
IC06
  Top 0.254: 30.16,90.81 31.11,91.76 32.7,91.76 A14.S2 | 30.16,90.81 28.26,88.9 28.26,66.04 20.95,58.74 20.95,54.61 B15.E2 | 30.16,90.81 40.32,90.81 41.27,91.76 45.4,91.76 A13.S2
IC07
  Top 0.254: 29.21,87.63 29.84,88.27 A14.T2 | 29.21,87.63 28.89,87.31 28.89,60.33 21.27,52.7 20,52.7 17.78,54.93 17.78,56.52 B15.D2 | 29.21,87.63 37.15,87.63 38.1,88.58 42.23,88.58 A13.T2
IC08
  Top 0.254: 39.69,81.28 41.27,81.28 42.23,82.23 A13.V2 | 39.69,81.28 35.88,81.28 34.92,82.23 30.8,82.23 A14.V2 | 39.69,81.28 47.31,88.9 47.31,99.06 46.67,99.69 32.7,99.69 22.23,89.22 18.1,89.22 A15.T2
IC09
  Top 0.254: B14.D2 30.8,56.83 34.92,56.83 35.88,55.88 41.27,55.88 42.23,56.83 B13.D2
  Bottom 0.254: A15.U2 20.95,85.09 20.95,78.11 28.89,70.17 28.89,58.74 29.84,57.78 B14.D2
IC10
  Bottom 0.254: 34.61,53.66 38.1,53.66 39.05,52.7 44.45,52.7 45.4,53.66 B13.E2 | 34.61,53.66 33.97,53.66 B14.E2 | 34.61,53.66 34.61,80.01 18.1,96.52 16.83,96.52 16.19,95.89 16.19,88.27 17.14,87.31 17.14,83.19 A15.V2
IC11
  Bottom 0.254: B13.H2 45.4,47.94 44.45,48.9 39.05,48.9 38.1,47.94 33.97,47.94 B14.H2 33.02,48.26 32.07,49.21 32.07,76.2 17.78,90.49 17.78,94.61 A15.R2
INT
  Top 0.254: 44.77,33.97 45.4,34.61 B13.M2 | 44.77,33.97 44.45,33.66 39.05,33.66 38.1,34.61 33.97,34.61 B14.M2 | 44.77,33.97 44.77,57.15 41.27,60.64 41.27,76.52 47.94,83.19 47.94,99.38 41.27,106.05 31.75,106.05 24.45,98.74 21.27,98.74 A15.P2
  Bottom 0.254: A05.L2 144.15,108.58 144.15,110.17 128.59,125.73 75.25,125.73 49.21,99.69 22.23,99.69 21.27,98.74 A15.P2
IOP1
  Top 0.254: A11.D2 68.9,126.68 73.03,126.68 73.98,125.73 79.38,125.73 80.33,126.68 A10.D2 81.28,126.36 81.28,122.24 85.41,118.11 85.41,97.79 82.87,95.25 82.87,86.36 66.99,70.48 66.99,50.16 71.44,45.72 84.14,45.72 91.76,53.34 91.76,57.15 93.03,58.42 107,58.42 124.46,40.96 | 124.46,40.96 127,40.96 127.95,40.01 133.35,40.01 134.3,40.96 B06.K2 | 124.46,40.96 122.87,40.96 B07.K2
IOP2
  Top 0.254: 82.23,109.86 82.55,109.86 83.5,110.81 A10.K2 | 82.23,109.86 77.15,109.86 76.2,110.81 72.07,110.81 A11.K2 | B06.M2 134.3,34.61 133.35,33.66 127.95,33.66 127,34.61 122.87,34.61 B07.M2 121.6,35.24 120.65,36.2 96.2,36.2 84.14,24.13 73.98,24.13 66.36,31.75 66.36,72.39 82.23,88.27 82.23,95.89 79.69,98.42 79.69,102.23 82.23,104.78 82.23,109.86
IOP4
  Top 0.254: B07.P2 122.87,28.26 127,28.26 127.95,27.3 133.35,27.3 134.3,28.26 B06.P2 | A11.R2 68.9,94.93 73.03,94.93 73.98,93.98 79.38,93.98 80.33,94.93 A10.R2
  Bottom 0.254: B07.P2 121.6,28.89 117.47,28.89 115.89,30.48 80.33,30.48 70.17,40.64 70.17,49.85 79.69,59.37 79.69,93.66 80.64,94.61 A10.R2
IOSKP
  Top 0.254: A15.N2 18.1,101.92 20,101.92 27.3,109.22 56.2,109.22 56.83,108.58 56.83,92.08 50.8,86.04 50.8,47.94 46.35,43.5 46.35,41.91 B13.K2 | A05.D2 145.1,127.32 149.22,127.32 150.18,128.27 158.75,128.27 203.2,83.82 203.2,12.06 192.41,1.27 26.99,1.27 16.19,12.06 16.19,22.23 33.02,39.05 33.02,40.64 B14.K2
  Bottom 0.254: B14.K2 33.97,40.96 38.1,40.96 39.05,40.01 41.91,40.01 42.86,40.96 45.4,40.96 B13.K2
IOTXY1\
  Bottom 0.254: A15.H2 21.27,117.79 25.4,117.79 26.99,119.38 66.67,119.38 67.63,120.33 A11.F2
IOTXY2
  Top 0.254: A15.D2 18.1,126.68 22.23,126.68 33.34,115.57 53.98,115.57 54.93,114.62 A12.J2 56.2,113.98 57.78,113.98 63.5,108.27 67.63,108.27 A11.L2
IOTXY2\
  Top 0.254: B05.J2 145.1,44.77 146.69,44.77 148.91,46.99 148.91,50.8 120.33,79.38 120.33,83.19 113.35,90.17 108.58,90.17 101.28,97.47 101.28,109.54 82.55,128.27 67.63,128.27 66.99,127.64 66.99,112.08 71.12,107.95 71.12,105.41 A11.M2
  Bottom 0.254: A12.P2 59.37,98.74 63.5,98.74 69.22,104.46 70.8,104.46 A11.M2
IOTXY4
  Top 0.254: A12.T2 56.2,89.22 60.33,89.22 61.91,90.81 69.85,90.81 70.8,91.76 A11.S2
  Bottom 0.254: B15.T2 18.1,19.37 22.23,19.37 30.16,27.3 46.67,27.3 75.88,56.52 75.88,85.72 71.75,89.85 71.75,91.44 A11.S2
IOTXZ1\
  Bottom 0.254: A10.F2 81.28,120.02 81.28,118.43 96.84,102.87 132.4,102.87 148.91,86.36 148.91,85.09 146.69,82.87 145.1,82.87 A05.V2
IOTXZ2
  Top 0.254: A12.S2 59.05,92.71 59.05,94.3 68.26,103.5 74.61,103.5 78.74,107.63 80.33,107.63 A10.L2
  Bottom 0.254: A05.U2 147,86.04 143.83,86.04 130.18,99.69 102.55,99.69 100.01,97.16 93.66,97.16 83.19,107.63 81.6,107.63 A10.L2
IOTXZ4
  Top 0.254: A10.S2 84.45,92.71 84.45,95.89 94.93,106.36 94.93,111.12 96.2,112.39 97.47,112.39 98.74,111.12 98.74,93.98 105.09,87.63 105.09,75.56 122.24,58.42 138.75,58.42 145.73,51.44 145.73,47.62 143.19,45.09 143.19,43.81 143.83,43.18 146.05,43.18 149.54,46.67 149.54,51.75 147.96,53.34 B05.E2 147.32,54.61 147.32,56.2 123.51,80.01 123.51,80.96 113.67,90.81 108.9,90.81 105.09,94.61 105.09,106.68 80.33,131.44 69.85,131.44 66.36,127.95 66.36,111.76 69.53,108.58 69.53,107.31 68.9,106.68 65.09,106.68 63.5,105.09 59.37,105.09 A12.M2
N$1
  Top 0.254: A10.V2 81.6,82.87 83.82,85.09 A10.U2
N$2
  Top 0.254: A16.F2 5.08,120.02 7.3,117.79 A16.H2
N$3
  Top 0.254: A16.R2 4.45,95.89 4.45,100.01 3.49,100.97 3.49,106.36 4.45,107.31 A16.L2
  Bottom 0.254: R1.1 5.08,146.05 13.02,146.05 14.29,147.32 14.92,147.32 15.88,146.37 15.88,129.54 3.49,117.16 3.49,109.54 4.45,108.58 A16.L2
N$4
  Top 0.254: A16.U2 7.3,86.04 5.08,88.27 A16.T2
  Bottom 0.254: R1.2 14.61,145.41 14.61,138.75 2.86,127 2.86,91.12 4.45,89.53 A16.T2
N$5
  Top 0.254: A10.J2 81.6,114.62 83.82,116.84 A10.H2
N$6
  Top 0.254: B04.H2 159.7,47.94 157.48,50.16 B04.F2
N$7
  Top 0.254: 155.89,23.81 155.89,12.06 156.84,11.11 156.84,3.81 R2.1 | 155.89,23.81 156.84,24.77 B04.R2 | 155.89,23.81 155.89,32.38 156.84,33.34 156.84,37.47 B04.L2
N$8
  Top 0.254: R2.2 167,3.81 167,7.3 160.66,13.65 160.66,15.24 B04.U2 159.7,16.19 157.48,18.41 B04.T2
N$9
  Top 0.254: A11.V2 68.9,82.87 71.12,85.09 A11.U2
N$10
  Top 0.254: A11.J2 68.9,114.62 71.12,116.84 A11.H2
N$11
  Top 0.254: A10.N2 81.28,100.97 83.5,98.74 A10.P2
N$12
  Top 0.254: A11.N2 68.58,100.97 70.8,98.74 A11.P2
N$13
  Top 0.254: A04.S2 160.02,92.71 160.02,97.79 A04.P2
N$14
  Top 0.254: A04.V2 156.84,83.19 156.84,87.31 155.89,88.27 155.89,93.66 156.84,94.61 A04.R2
N$15
  Bottom 0.254: J1.2 180.02,3.81 180.02,7.3 187.64,14.92 187.64,29.84 183.83,33.66 183.83,38.73 182.56,40.01 172.4,40.01 171.77,40.64 171.77,54.61 175.58,58.42 180.97,58.42 181.93,57.47 B02.D2
N$16
  Top 0.254: B01.H2 197.8,47.94 195.58,50.16 B01.F2
N$17
  Top 0.254: J2.2 192.09,3.81 192.09,13.97 187.01,19.05 187.01,52.39 186.06,53.34 B02.E2
PSM
  Top 0.254: A05.H2 148.27,117.79 149.86,117.79 156.84,124.78 156.84,126.36 A04.D2 157.8,126.68 159.38,126.68 193.68,92.39 193.68,66.99 196.53,64.14 196.53,62.87 192.09,58.42 169.23,58.42 168.59,57.78 168.59,41.27 | 168.59,41.27 168.59,12.06 169.23,11.43 169.23,3.81 J1.1 | 168.59,41.27 172.72,45.4 172.72,46.99 B03.H2
PWRCLR\
  Top 0.254: 130.18,11.43 124.78,11.43 123.83,12.38 119.7,12.38 B07.V2 118.43,13.02 114.3,13.02 110.17,17.14 68.26,17.14 49.21,36.2 | 130.18,11.43 131.13,12.38 B06.V2 | 130.18,11.43 138.75,11.43 142.88,15.56 147,15.56 B05.U2 | 49.21,36.2 54.29,41.27 54.29,80.96 55.24,81.92 A12.V2 | 49.21,36.2 46.04,33.02 35.88,33.02 17.78,14.92 17.78,13.34 B15.V2
RCLE\
  Top 0.254: A12.L2 54.93,107.63 50.8,107.63 49.85,106.68 25.72,106.68 11.43,92.39 8.57,92.39 A16.S2
  Bottom 0.254: B15.J2 17.14,45.09 17.14,49.21 16.19,50.16 16.19,64.14 17.46,65.41 21.27,65.41 21.91,66.04 21.91,75.25 8.26,88.9 8.26,91.44 A16.S2
RCLO
  Top 0.254: B15.S2 20.95,22.86 20.95,26.04 34.61,39.69 34.61,41.91 30.16,46.35 19.05,46.35 2.86,62.55 2.86,124.78 4.45,126.36 A16.D2 5.4,127.32 6.35,128.27 49.85,128.27 50.8,127.32 54.93,127.32 A12.D2
RRE
  Top 0.254: B03.M2 172.72,34.29 172.72,30.16 171.13,28.57 171.13,2.86 170.18,1.91 156.53,1.91 148.91,9.53 148.91,25.4 143.19,31.11 143.19,34.92 152.08,43.81 152.08,52.39 124.14,80.33 124.14,98.42 119.06,103.5 108.9,103.5 107.63,104.78 107.63,108.58 84.14,132.08 68.9,132.08 65.72,128.91 4.76,128.91 1.59,125.73 1.59,55.88 17.14,40.32 17.14,38.73 B15.L2
TCLO
  Bottom 0.254: 152.4,55.88 155.57,55.88 156.53,56.83 B04.D2 | 152.4,55.88 150.18,55.88 149.22,56.83 145.1,56.83 B05.D2 | 152.4,55.88 152.4,90.17 146.37,96.2 146.37,101.6 125.41,122.56 80.01,122.56 79.06,121.6 79.06,110.49 59.05,90.49 59.05,86.36 A12.U2
TSO
  Top 0.254: B03.D2 170.5,56.83 174.62,56.83 175.58,55.88 193.68,55.88 194.63,56.83 B01.D2
  Bottom 0.254: B01.D2 194.94,56.52 193.99,55.56 193.99,15.88 182.56,4.45 182.56,3.81 J2.1 181.93,2.54 180.66,1.27 33.34,1.27 6.03,28.57 6.03,89.53 3.49,92.08 3.49,95.89 6.03,98.42 6.03,118.75 18.73,131.44 18.73,136.53 20,137.79 21.27,137.79 21.91,137.16 21.91,129.54 17.78,125.41 17.78,121.28 A15.F2
VCC
  Top 0.508: B05.A2 148.27,66.36 152.4,66.36 153.67,65.09 158.43,65.09 159.7,66.36 B04.A2 160.97,66.36 165.1,66.36 166.37,65.09 171.13,65.09 172.4,66.36 B03.A2 | 158.59,135.1 159.7,136.21 A04.A2 | 158.59,135.1 158.43,134.94 153.67,134.94 152.4,136.21 148.27,136.21 A05.A2 | A03.A2 172.4,136.21 168.28,136.21 167,134.94 158.75,134.94 158.59,135.1 | B11.A2 72.07,66.36 76.2,66.36 77.47,65.09 82.23,65.09 83.5,66.36 B10.A2 | 18.89,135.1 20,136.21 A15.A2 | 18.89,135.1 18.73,134.94 13.97,134.94 12.7,136.21 8.57,136.21 A16.A2 | A11.A2 70.8,136.21 66.67,136.21 65.41,134.94 19.05,134.94 18.89,135.1
  Bottom 0.508: 185.58,57.31 187.32,59.05 187.32,60.01 | 185.58,57.31 173.35,45.09 173.35,41.91 B03.K2 | 187.32,60.01 187.32,64.77 186.06,66.04 B02.A2 | 185.58,57.31 185.42,57.47 176.53,66.36 173.67,66.36 B03.A2 172.72,67.31 172.72,84.14 171.45,85.41 171.45,134.62 172.72,135.89 A03.A2 | 187.32,60.01 193.68,66.36 197.8,66.36 B01.A2 | 82.39,135.1 83.5,136.21 A10.A2 | 82.39,135.1 82.23,134.94 77.47,134.94 76.2,136.21 72.07,136.21 A11.A2 | 20.32,69.22 20.32,75.88 6.67,89.53 6.67,91.44 6.35,91.76 6.35,94.93 12.7,101.28 12.7,124.46 20.32,132.08 20.32,135.89 A15.A2 | 20.32,69.22 20.32,67.31 B15.A2 | 20.32,69.22 12.7,61.59 12.7,47.31 17.14,42.86 49.53,42.86 71.12,64.45 71.12,66.04 B11.A2 | A05.A2 147,136.21 142.88,136.21 141.6,134.94 82.55,134.94 82.39,135.1

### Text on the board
tOrigins: Need the Access Holes for Screws?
